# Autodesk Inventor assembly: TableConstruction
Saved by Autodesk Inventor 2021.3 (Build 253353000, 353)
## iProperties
Created: 2022-04
Part Number: TableConstruction
Document SubType Name: Assembly
Designer: Administrator
Title: TableConstruction v12
Author: Administrator
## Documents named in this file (6)
- c:\worker\convert-fusion-r02\tmp\job-1\122\output\files\a13a8e66-f23c-4ace-beb1-2561a71d4785\b22d49c6-8b42-48f1-bd00-26c52f3c15af.iam
- c:\worker\convert-fusion-r02\tmp\job-1\122\output\files\a13a8e66-f23c-4ace-beb1-2561a71d4785\150mm Rail v2.ipt
- c:\worker\convert-fusion-r02\tmp\job-1\122\output\files\a13a8e66-f23c-4ace-beb1-2561a71d4785\8809T62_1-1 2  Long Corner Bracket for 1-1 2  Rail High Aluminum Bolt-Together Framing v1.ipt
- c:\worker\convert-fusion-r02\tmp\job-1\122\output\files\a13a8e66-f23c-4ace-beb1-2561a71d4785\4931T333_Bracket Fastener Set for 1-1 2 Square Rail Bolt-Together Framing v1.ipt
- c:\worker\convert-fusion-r02\tmp\job-1\122\output\files\a13a8e66-f23c-4ace-beb1-2561a71d4785\200 mm rail v1.ipt
- c:\worker\convert-fusion-r02\tmp\job-1\122\output\files\a13a8e66-f23c-4ace-beb1-2561a71d4785\Base Top v30.ipt
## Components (21 placed, 5 different names)
1. 150mm Rail v2:2
2. 8809T62_1-1 2  Long Corner Bracket for 1-1 2  Rail High Aluminum Bolt-Together Framing v1:1
3. 150mm Rail v2:4
4. 4931T333_Bracket Fastener Set for 1-1 2 Square Rail Bolt-Together Framing v1:2
5. 8809T62_1-1 2  Long Corner Bracket for 1-1 2  Rail High Aluminum Bolt-Together Framing v1:2
6. 150mm Rail v2:5
7. 4931T333_Bracket Fastener Set for 1-1 2 Square Rail Bolt-Together Framing v1:3
8. 8809T62_1-1 2  Long Corner Bracket for 1-1 2  Rail High Aluminum Bolt-Together Framing v1:3
9. 150mm Rail v2:6
10. 4931T333_Bracket Fastener Set for 1-1 2 Square Rail Bolt-Together Framing v1:5
11. 8809T62_1-1 2  Long Corner Bracket for 1-1 2  Rail High Aluminum Bolt-Together Framing v1:5
12. 4931T333_Bracket Fastener Set for 1-1 2 Square Rail Bolt-Together Framing v1:6
13. 4931T333_Bracket Fastener Set for 1-1 2 Square Rail Bolt-Together Framing v1:7
14. 4931T333_Bracket Fastener Set for 1-1 2 Square Rail Bolt-Together Framing v1:8
15. 200 mm rail v1:1
16. Base Top v30:1
17. 4931T333_Bracket Fastener Set for 1-1 2 Square Rail Bolt-Together Framing v1:9
18. 4931T333_Bracket Fastener Set for 1-1 2 Square Rail Bolt-Together Framing v1:10
19. 200 mm rail v1:2
20. 4931T333_Bracket Fastener Set for 1-1 2 Square Rail Bolt-Together Framing v1:11
21. 4931T333_Bracket Fastener Set for 1-1 2 Square Rail Bolt-Together Framing v1:12
